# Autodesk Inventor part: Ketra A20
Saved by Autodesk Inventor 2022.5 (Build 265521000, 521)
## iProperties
Created: 2025-02
Part Number: Ketra A20
Material: Generic
Document SubType Name: Modeling
Designer: AdminForWorker
Density: 1 g/cm^3
Appearance: Default
Title: Ketra A20
Author: AdminForWorker
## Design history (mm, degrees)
feature "Body1"
body "Solid1"
